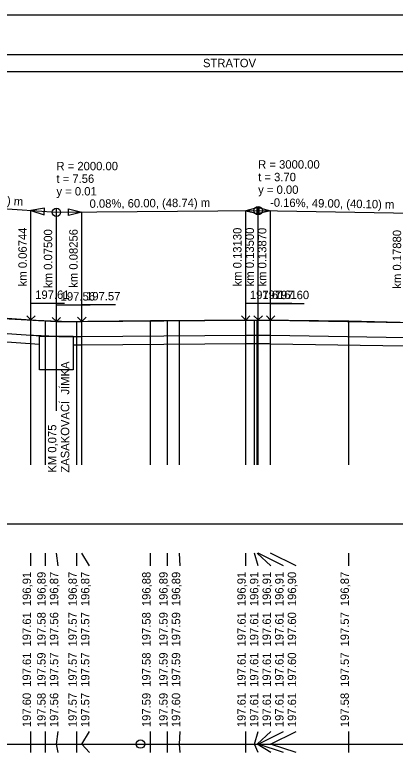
# Model space of a CAD drawing. Extents: x -24.9 to 20.5, y -71.8 to 17.3.
# Drawn here: x -3.79 to 7.53, y -4.65 to 17.31 of the extents above; entities that cross this region are included whole.
import ezdxf

# ---------------------------------------------------------------- set-up
doc = ezdxf.new("R2010")
doc.units = 0
for name, color, linetype in [('Implicitní', 7, 'Continuous'), ('KONSTRUKCE_L', 7, 'Continuous'), ('KOTY_L', 7, 'Continuous'), ('KOTY_N', 7, 'Continuous'), ('KOTY_S', 7, 'Continuous'), ('KOTY_T', 7, 'Continuous'), ('KOTY_VP', 7, 'Continuous'), ('LEGENDA', 7, 'Continuous'), ('Nová vrstva (0)', 7, 'Continuous'), ('PR_SKLON_L', 7, 'Continuous'), ('ROVINA_L', 7, 'Continuous'), ('ROVINA_O', 7, 'Continuous'), ('SKLON_POMERY', 7, 'Continuous'), ('TABULKY_L', 7, 'Continuous'), ('TEREN_L', 7, 'Continuous'), ('V_POLYGON', 7, 'Continuous'), ('V_POLYGON_ZO', 7, 'Continuous')]:
    doc.layers.add(name, color=color, linetype=linetype)

msp = doc.modelspace()

# ---------------------------------------------------------------- linework, layer by layer
at = {"layer": 'Implicitní'}
msp.add_lwpolyline([(-24.886, 17.307), (20.536, 17.307), (20.536, -12.393), (-24.886, -12.393)], close=True, dxfattribs=at)
at = {"layer": 'KONSTRUKCE_L'}
for p, q in [((-6.85, 8.022), (-3.309, 7.783)), ((-3.309, 7.783), (-3.233, 7.778)), ((-3.233, 7.778), (-3.158, 7.774)), ((-3.158, 7.774), (-3.082, 7.769)), ((-3.082, 7.769), (-3.006, 7.765)), ((-3.006, 7.765), (-2.931, 7.762)), ((-2.931, 7.762), (-2.855, 7.758)), ((-2.855, 7.758), (-2.779, 7.755)), ((-2.779, 7.755), (-2.704, 7.752)), ((-2.704, 7.752), (-2.628, 7.749)), ((-2.628, 7.749), (-2.552, 7.747)), ((-2.552, 7.747), (-2.477, 7.745)), ((-2.477, 7.745), (-2.401, 7.743)), ((-2.401, 7.743), (-2.326, 7.741)), ((-2.326, 7.741), (-2.25, 7.74)), ((-2.25, 7.74), (-2.174, 7.739)), ((-2.174, 7.739), (-2.099, 7.739)), ((-2.099, 7.739), (-2.023, 7.738)), ((-2.023, 7.738), (-1.947, 7.738)), ((-1.947, 7.738), (-1.872, 7.738)), ((-1.872, 7.738), (-1.796, 7.739)), ((-1.796, 7.739), (3.078, 7.779)), ((3.078, 7.779), (3.115, 7.78)), ((3.115, 7.78), (3.152, 7.78)), ((3.152, 7.78), (3.189, 7.78)), ((3.189, 7.78), (3.226, 7.78)), ((3.226, 7.78), (3.263, 7.78)), ((3.263, 7.78), (3.3, 7.78)), ((3.3, 7.78), (3.337, 7.78)), ((3.337, 7.78), (3.374, 7.78)), ((3.374, 7.78), (3.411, 7.78)), ((3.411, 7.78), (3.448, 7.78)), ((3.448, 7.78), (3.485, 7.78)), ((3.485, 7.78), (3.522, 7.78)), ((3.522, 7.78), (3.559, 7.78)), ((3.559, 7.78), (3.595, 7.779)), ((3.595, 7.779), (3.632, 7.779)), ((3.632, 7.779), (3.669, 7.779)), ((3.669, 7.779), (3.706, 7.778)), ((3.706, 7.778), (3.743, 7.778)), ((3.743, 7.778), (3.78, 7.777)), ((3.78, 7.777), (3.817, 7.776)), ((3.817, 7.776), (7.827, 7.711))]:
    msp.add_line(p, q, dxfattribs=at)
at = {"layer": 'KOTY_L'}
for p, q in [((-3.309, 3.923), (-3.309, 8.226)), ((-2.873, 3.923), (-2.873, 8.201)), ((-2.552, 5.526), (-2.552, 8.183)), ((-1.947, 3.923), (-1.947, 8.189)), ((-1.796, 3.923), (-1.796, 8.191)), ((0.248, 3.923), (0.248, 8.213)), ((0.755, 3.923), (0.755, 8.216)), ((1.108, 3.923), (1.108, 8.218)), ((3.078, 3.923), (3.078, 8.23)), ((3.337, 3.923), (3.337, 8.232)), ((3.417, 3.923), (3.417, 8.232)), ((3.448, 3.923), (3.448, 8.232)), ((3.817, 3.923), (3.817, 8.228)), ((6.148, 3.923), (6.148, 8.203)), ((-3.309, 0.923), (-3.309, 1.298)), ((-2.873, 0.923), (-2.873, 1.298)), ((-2.498, 0.923), (-2.552, 1.298)), ((-1.947, 0.923), (-1.947, 1.298)), ((-1.572, 0.923), (-1.796, 1.298)), ((0.248, 0.923), (0.248, 1.298)), ((0.755, 0.923), (0.755, 1.298)), ((1.13, 0.923), (1.108, 1.298)), ((3.078, 0.923), (3.078, 1.298)), ((3.453, 0.923), (3.337, 1.298)), ((3.828, 0.923), (3.417, 1.298)), ((4.203, 0.923), (3.448, 1.298)), ((4.578, 0.923), (3.817, 1.298)), ((6.148, 0.923), (6.148, 1.298)), ((-3.309, -2.678), (-3.309, -2.678)), ((-2.873, -2.678), (-2.873, -2.678)), ((-2.498, -2.678), (-2.498, -2.678)), ((-1.947, -2.678), (-1.947, -2.678)), ((-1.572, -2.678), (-1.572, -2.678)), ((0.248, -2.678), (0.248, -2.678)), ((0.755, -2.678), (0.755, -2.678)), ((1.13, -2.678), (1.13, -2.678)), ((3.078, -2.678), (3.078, -2.678)), ((3.453, -2.678), (3.453, -2.678)), ((3.828, -2.678), (3.828, -2.678)), ((4.203, -2.678), (4.203, -2.678)), ((4.578, -2.678), (4.578, -2.678)), ((6.148, -2.678), (6.148, -2.678)), ((-3.309, -4.378), (-3.309, -4.003)), ((-2.873, -4.378), (-2.873, -4.003)), ((-2.552, -4.378), (-2.498, -4.003)), ((-1.947, -4.378), (-1.947, -4.003)), ((-1.796, -4.378), (-1.572, -4.003)), ((0.248, -4.378), (0.248, -4.003)), ((0.755, -4.378), (0.755, -4.003)), ((1.108, -4.378), (1.13, -4.003)), ((3.078, -4.378), (3.078, -4.003)), ((3.337, -4.378), (3.453, -4.003)), ((3.417, -4.378), (3.828, -4.003)), ((3.448, -4.378), (4.203, -4.003)), ((3.817, -4.378), (4.578, -4.003)), ((6.148, -4.378), (6.148, -4.003))]:
    msp.add_line(p, q, dxfattribs=at)
at = {"layer": 'KOTY_S'}
for p, q in [((-3.309, -4.628), (-3.309, -4.378)), ((-2.873, -4.628), (-2.873, -4.378)), ((-2.498, -4.628), (-2.552, -4.378)), ((-1.947, -4.628), (-1.947, -4.378)), ((-1.572, -4.628), (-1.796, -4.378)), ((0.248, -4.628), (0.248, -4.378)), ((0.755, -4.628), (0.755, -4.378)), ((1.13, -4.628), (1.108, -4.378)), ((3.078, -4.628), (3.078, -4.378)), ((3.453, -4.628), (3.337, -4.378)), ((3.828, -4.628), (3.417, -4.378)), ((4.203, -4.628), (3.448, -4.378)), ((4.578, -4.628), (3.817, -4.378)), ((6.148, -4.628), (6.148, -4.378))]:
    msp.add_line(p, q, dxfattribs=at)
at = {"layer": 'Nová vrstva (0)'}
for p, q in [((-6.867, 7.772), (-3.06, 7.516)), ((-2.051, 7.488), (-2.024, 7.488)), ((-2.023, 7.488), (-1.948, 7.488)), ((-1.947, 7.488), (-1.871, 7.488)), ((-1.87, 7.488), (-1.794, 7.489)), ((-1.794, 7.489), (3.08, 7.529)), ((3.08, 7.529), (3.117, 7.53)), ((3.116, 7.53), (3.153, 7.53)), ((3.153, 7.53), (3.19, 7.53)), ((3.19, 7.53), (3.227, 7.53)), ((3.226, 7.53), (3.263, 7.53)), ((3.263, 7.53), (3.3, 7.53)), ((3.3, 7.53), (3.337, 7.53)), ((3.336, 7.53), (3.373, 7.53)), ((3.373, 7.53), (3.41, 7.53)), ((3.41, 7.53), (3.447, 7.53)), ((3.446, 7.53), (3.483, 7.53)), ((3.483, 7.53), (3.52, 7.53)), ((3.52, 7.53), (3.557, 7.53)), ((3.556, 7.53), (3.593, 7.529)), ((3.593, 7.529), (3.63, 7.529)), ((3.63, 7.529), (3.667, 7.529)), ((3.666, 7.529), (3.703, 7.528)), ((3.703, 7.528), (3.74, 7.528)), ((3.74, 7.528), (3.777, 7.527)), ((3.777, 7.527), (3.814, 7.526)), ((3.813, 7.526), (7.823, 7.461))]:
    msp.add_line(p, q, dxfattribs=at)
msp.add_lwpolyline([(-3.052, 7.747), (-2.052, 7.747), (-2.052, 6.747), (-3.052, 6.747)], close=True, dxfattribs=at)
at = {"layer": 'PR_SKLON_L'}
msp.add_line((-10.052, 2.173), (14.148, 2.173), dxfattribs=at)
at = {"layer": 'ROVINA_L'}
msp.add_line((-10.052, -4.378), (14.148, -4.378), dxfattribs=at)
at = {"layer": 'ROVINA_O'}
msp.add_circle((-0.052, -4.378), 0.125, dxfattribs=at)
at = {"layer": 'SKLON_POMERY'}
for p, q in [((-7.752, 11.783), (-2.552, 11.433)), ((-3.309, 8.233), (-3.309, 11.483)), ((-2.552, 11.433), (-2.552, 11.558)), ((-2.552, 11.433), (3.448, 11.482)), ((-2.552, 8.183), (-2.552, 11.433)), ((-1.796, 8.189), (-1.796, 11.439)), ((3.078, 8.229), (3.078, 11.479)), ((3.448, 11.482), (3.448, 11.607)), ((3.448, 8.232), (3.448, 11.482)), ((3.448, 11.482), (8.348, 11.402)), ((3.817, 8.226), (3.817, 11.476))]:
    msp.add_line(p, q, dxfattribs=at)
for points in [[(-3.309, 11.483), (-2.916, 11.357), (-2.903, 11.556), (-3.309, 11.483)], [(-1.796, 11.439), (-2.195, 11.335), (-2.197, 11.535), (-1.796, 11.439)], [(3.078, 11.479), (3.478, 11.383), (3.477, 11.583), (3.078, 11.479)], [(3.817, 11.476), (3.416, 11.383), (3.419, 11.583), (3.817, 11.476)]]:
    msp.add_lwpolyline(points, close=True, dxfattribs=at)
for points in [[(-3.434, 8.358), (-3.309, 8.233), (-3.184, 8.358), (-3.309, 8.233), (-3.309, 8.733), (-2.309, 8.733)], [(-2.677, 8.308), (-2.552, 8.183), (-2.427, 8.308), (-2.552, 8.183), (-2.552, 8.683), (-1.552, 8.683)], [(-1.921, 8.314), (-1.796, 8.189), (-1.671, 8.314), (-1.796, 8.189), (-1.796, 8.689), (-0.796, 8.689)], [(2.953, 8.354), (3.078, 8.229), (3.203, 8.354), (3.078, 8.229), (3.078, 8.729), (4.078, 8.729)], [(3.323, 8.357), (3.448, 8.232), (3.573, 8.357), (3.448, 8.232), (3.448, 8.732), (4.448, 8.732)], [(3.692, 8.351), (3.817, 8.226), (3.942, 8.351), (3.817, 8.226), (3.817, 8.726), (4.817, 8.726)]]:
    msp.add_lwpolyline(points, dxfattribs=at)
for centre in [(-2.552, 11.433), (3.448, 11.482)]:
    msp.add_circle(centre, 0.125, dxfattribs=at)
at = {"layer": 'TABULKY_L'}
for p, q in [((-10.052, 16.122), (14.148, 16.122)), ((-10.052, 15.622), (14.148, 15.622))]:
    msp.add_line(p, q, dxfattribs=at)
at = {"layer": 'TEREN_L'}
for p, q in [((-5.152, 8.332), (-2.552, 8.183)), ((-2.552, 8.183), (0.248, 8.213)), ((0.248, 8.213), (3.448, 8.232)), ((3.448, 8.232), (6.148, 8.203)), ((6.148, 8.203), (8.348, 8.152))]:
    msp.add_line(p, q, dxfattribs=at)
at = {"layer": 'V_POLYGON'}
for p, q in [((-6.85, 8.472), (-3.309, 8.233)), ((-1.796, 8.189), (3.078, 8.229)), ((3.817, 8.226), (7.827, 8.161))]:
    msp.add_line(p, q, dxfattribs=at)
for points in [[(-3.309, 8.233), (-3.233, 8.228), (-3.158, 8.224), (-3.082, 8.219), (-3.006, 8.215), (-2.931, 8.212), (-2.855, 8.208), (-2.779, 8.205), (-2.704, 8.202), (-2.628, 8.199), (-2.552, 8.197), (-2.477, 8.195), (-2.401, 8.193), (-2.326, 8.191), (-2.25, 8.19), (-2.174, 8.189), (-2.099, 8.189), (-2.023, 8.188), (-1.947, 8.188), (-1.872, 8.188), (-1.796, 8.189)], [(3.078, 8.229), (3.115, 8.23), (3.152, 8.23), (3.189, 8.23), (3.226, 8.23), (3.263, 8.23), (3.3, 8.23), (3.337, 8.23), (3.374, 8.23), (3.411, 8.23), (3.448, 8.23), (3.485, 8.23), (3.522, 8.23), (3.559, 8.23), (3.595, 8.229), (3.632, 8.229), (3.669, 8.229), (3.706, 8.228), (3.743, 8.228), (3.78, 8.227), (3.817, 8.226)]]:
    msp.add_lwpolyline(points, dxfattribs=at)
at = {"layer": 'V_POLYGON_ZO'}
for p, q in [((-3.309, 8.233), (-2.552, 8.183)), ((-2.552, 8.183), (-1.796, 8.189)), ((3.078, 8.229), (3.448, 8.232)), ((3.448, 8.232), (3.817, 8.226))]:
    msp.add_line(p, q, dxfattribs=at)

# ---------------------------------------------------------------- texts
at = {"layer": 'KOTY_N'}
for s, p in [('197.61', (-3.309, -2.678)), ('197.59', (-2.873, -2.678)), ('197.57', (-2.498, -2.678)), ('197.57', (-1.947, -2.678)), ('197.57', (-1.572, -2.678)), ('197.58', (0.248, -2.678)), ('197.59', (0.755, -2.678)), ('197.59', (1.13, -2.678)), ('197.61', (3.078, -2.678)), ('197.61', (3.453, -2.678)), ('197.61', (3.828, -2.678)), ('197.61', (4.203, -2.678)), ('197.60', (4.578, -2.678)), ('197.57', (6.148, -2.678))]:
    msp.add_text(s, height=0.25, rotation=90, dxfattribs=at).set_placement(p)
at = {"layer": 'KOTY_T'}
for s, p in [('197.60', (-3.309, -3.878)), ('197.58', (-2.873, -3.878)), ('197.56', (-2.498, -3.878)), ('197.57', (-1.947, -3.878)), ('197.57', (-1.572, -3.878)), ('197.59', (0.248, -3.878)), ('197.59', (0.755, -3.878)), ('197.60', (1.13, -3.878)), ('197.61', (3.078, -3.878)), ('197.61', (3.453, -3.878)), ('197.61', (3.828, -3.878)), ('197.61', (4.203, -3.878)), ('197.61', (4.578, -3.878)), ('197.58', (6.148, -3.878))]:
    msp.add_text(s, height=0.25, rotation=90, dxfattribs=at).set_placement(p)
at = {"layer": 'KOTY_VP'}
for s, p in [('197.61', (-3.309, -1.478)), ('197.58', (-2.873, -1.478)), ('197.56', (-2.498, -1.478)), ('197.57', (-1.947, -1.478)), ('197.57', (-1.572, -1.478)), ('197.58', (0.248, -1.478)), ('197.59', (0.755, -1.478)), ('197.59', (1.13, -1.478)), ('197.61', (3.078, -1.478)), ('197.61', (3.453, -1.478)), ('197.61', (3.828, -1.478)), ('197.61', (4.203, -1.478)), ('197.60', (4.578, -1.478)), ('197.57', (6.148, -1.478))]:
    msp.add_text(s, height=0.25, rotation=90, dxfattribs=at).set_placement(p)
at = {"layer": 'LEGENDA'}
msp.add_text('STRATOV', height=0.25, dxfattribs=at).set_placement((1.807, 15.747))
at = {"layer": 'Nová vrstva (0)'}
for s, p in [('ZASAKOVACÍ  JÍMKA', (-2.171, 3.691)), ('KM 0,075', (-2.555, 3.691)), ('196,91', (-3.309, -0.278)), ('196,89', (-2.873, -0.278)), ('196,87', (-2.498, -0.278)), ('196,87', (-1.947, -0.278)), ('196,87', (-1.572, -0.278)), ('196,88', (0.248, -0.278)), ('196,89', (0.755, -0.278)), ('196,89', (1.13, -0.278)), ('196,91', (3.078, -0.278)), ('196,91', (3.453, -0.278)), ('196,91', (3.828, -0.278)), ('196,91', (4.203, -0.278)), ('196,90', (4.578, -0.278)), ('196,87', (6.148, -0.278))]:
    msp.add_text(s, height=0.25, rotation=90, dxfattribs=at).set_placement(p)
at = {"layer": 'SKLON_POMERY'}
for s, p in [('R = 3000.00', (3.448, 12.732)), ('R = 2000.00', (-2.552, 12.683)), ('t = 7.56', (-2.552, 12.308)), ('t = 3.70', (3.448, 12.357)), ('y = 0.01', (-2.552, 11.933)), ('y = 0.00', (3.448, 11.982)), ('197.61', (-3.184, 8.858)), ('197.56', (-2.427, 8.808)), ('197.57', (-1.671, 8.814)), ('197.61', (3.203, 8.854)), ('197.61', (3.573, 8.857)), ('197.60', (3.942, 8.851))]:
    msp.add_text(s, height=0.25, dxfattribs=at).set_placement(p)
for s, rotation, p in [('-0.67%, 52.00, (35.41) m', 356.1494, (-7.239, 11.874)), ('0.08%, 60.00, (48.74) m', 0.4774, (-1.566, 11.566)), ('-0.16%, 49.00, (40.10) m', 359.0646, (3.8, 11.602)), ('km 0.06744', 90, (-3.434, 9.233)), ('km 0.07500', 90, (-2.677, 9.183)), ('km 0.08256', 90, (-1.921, 9.189)), ('km 0.13130', 90, (2.953, 9.229)), ('km 0.13500', 90, (3.323, 9.232)), ('km 0.13870', 90, (3.692, 9.226)), ('km 0.17880', 90, (7.702, 9.161))]:
    msp.add_text(s, height=0.25, rotation=rotation, dxfattribs=at).set_placement(p)

doc.saveas('drawing.dxf')
